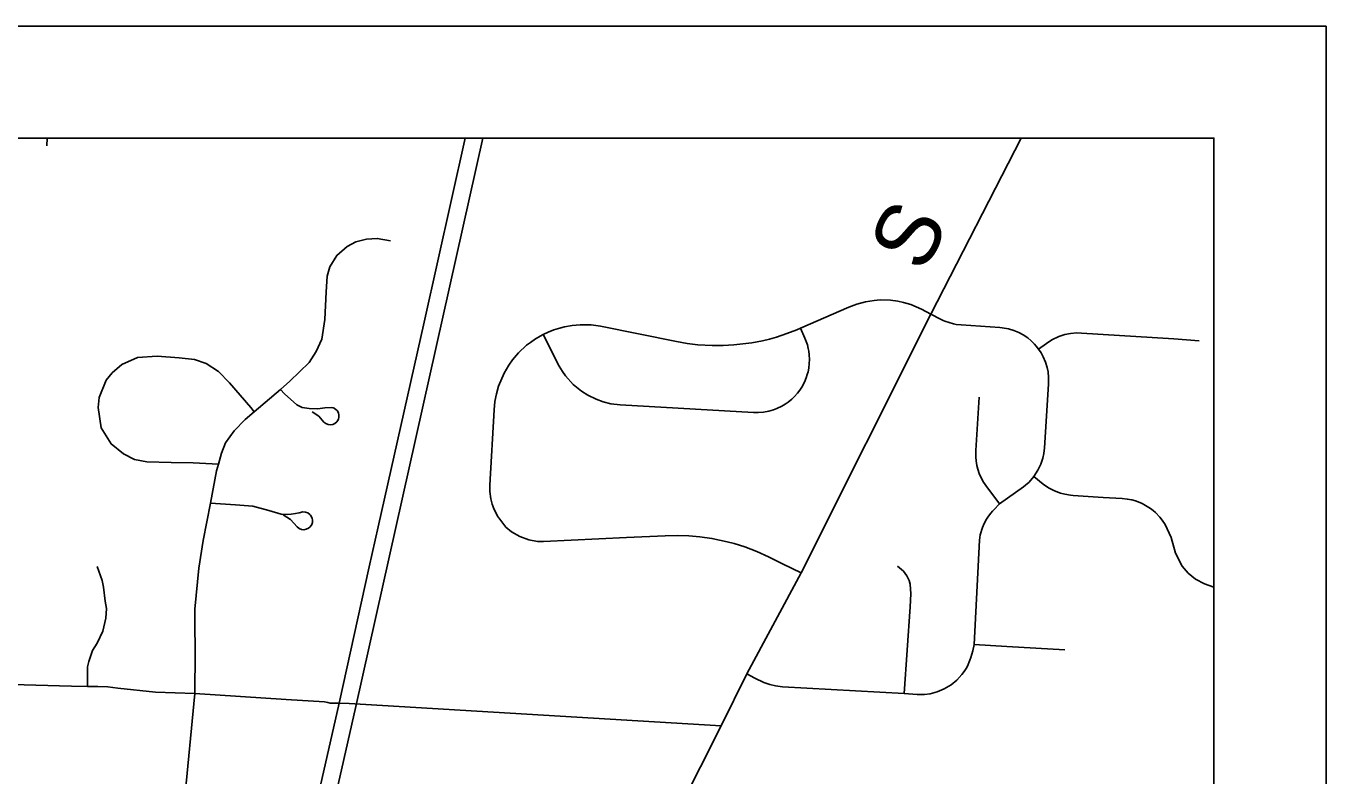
# Model space of a CAD drawing. Extents: x 0 to 34, y 0 to 22.
# Drawn here: x 9.258 to 10.418, y 9.615 to 10.284 of the extents above; entities that cross this region are included whole.
import ezdxf

# ---------------------------------------------------------------- set-up
doc = ezdxf.new("R2010")
doc.units = 0
for name, color, linetype in [('GM_X_Corporation', 7, 'Continuous'), ('GM_X_County_Road', 7, 'Continuous'), ('GM_X_County_Road_Text', 7, 'Continuous'), ('GM_X_Rail_Line', 7, 'Continuous'), ('GM_X_State_Route', 7, 'Continuous'), ('GM_X_Township_Road', 7, 'Continuous'), ('SH_Data', 7, 'Continuous')]:
    doc.layers.add(name, color=color, linetype=linetype)

msp = doc.modelspace()

# ---------------------------------------------------------------- linework, layer by layer
at = {"layer": 'GM_X_Corporation'}
for points in [[(10.3182, 6.9963), (10.3182, 10.1841), (3.5182, 10.1841)], [(10.3182, 6.9963), (10.3182, 10.1841), (8.0168, 10.1841), (8.012, 10.1113), (7.9906, 9.8037), (7.9854, 9.7171), (7.9173, 8.8475), (7.9043, 8.6471), (7.8824, 8.2446), (7.8769, 8.1664), (7.8619, 7.9568), (7.8248, 7.359), (7.8118, 7.1421)]]:
    msp.add_lwpolyline(points, dxfattribs=at)
at = {"layer": 'GM_X_County_Road'}
msp.add_lwpolyline([(9.2983, 8.492), (9.3206, 8.5378), (9.4763, 8.8512), (9.532, 8.9642), (9.6643, 9.2319), (9.7654, 9.4338), (9.7887, 9.4806), (9.823, 9.5499), (9.8784, 9.6595), (9.9012, 9.7059), (9.9498, 9.7963), (10.0655, 10.0271), (10.1462, 10.1841)], dxfattribs=at)
at = {"layer": 'GM_X_Rail_Line'}
msp.add_lwpolyline([(8.9712, 7.0765), (9.0871, 7.5941), (9.3068, 8.5932), (9.5523, 9.677), (9.6655, 10.1841)], dxfattribs=at)
at = {"layer": 'GM_X_State_Route'}
for points in [[(9.5722, 9.8371), (9.5895, 9.9139), (9.6132, 10.0197), (9.6499, 10.1841)], [(9.5019, 9.5239), (9.5372, 9.6798), (9.5642, 9.8016), (9.5722, 9.8371)]]:
    msp.add_lwpolyline(points, dxfattribs=at)
at = {"layer": 'GM_X_Township_Road'}
for p, q in [((9.2764, 10.1771), (9.2768, 10.1841)), ((9.4087, 9.725), (9.4086, 9.7521)), ((9.4084, 9.6884), (9.4087, 9.725))]:
    msp.add_line(p, q, dxfattribs=at)
for points in [[(9.4086, 9.7521), (9.4086, 9.7638), (9.4122, 9.8004), (9.4158, 9.825), (9.4224, 9.8583), (9.4278, 9.8873), (9.4295, 9.8931), (9.4324, 9.903), (9.436, 9.9121), (9.4435, 9.9228), (9.4534, 9.933), (9.4616, 9.9399), (9.4849, 9.9599), (9.4932, 9.9671), (9.5106, 9.9838), (9.5168, 9.9936), (9.5218, 10.0047), (9.5246, 10.0221), (9.5257, 10.0468), (9.5266, 10.0608), (9.529, 10.0691), (9.5353, 10.0794), (9.5445, 10.0875), (9.5522, 10.0915), (9.5616, 10.0938), (9.5714, 10.0946), (9.5831, 10.0924)], [(9.68, 9.8451), (9.6794, 9.8459), (9.6757, 9.8528), (9.6739, 9.8574), (9.6726, 9.8622), (9.6718, 9.8687), (9.6717, 9.8745), (9.6756, 9.9417), (9.6764, 9.9491), (9.6777, 9.956), (9.6797, 9.9627), (9.6846, 9.9743), (9.6889, 9.9816), (9.6921, 9.9862), (9.6975, 9.9924), (9.7047, 9.9992), (9.708, 10.0018), (9.7126, 10.0049), (9.7194, 10.0088), (9.7238, 10.0109), (9.729, 10.013), (9.733, 10.0143), (9.7385, 10.0157), (9.7454, 10.0169), (9.7524, 10.0175), (9.758, 10.0176), (9.7622, 10.0174), (9.7705, 10.0163), (9.8384, 10.0026), (9.848, 10.0009), (9.8576, 9.9997), (9.8704, 9.999), (9.8801, 9.999), (9.8897, 9.9995), (9.9057, 10.0015), (9.9152, 10.0033), (9.9215, 10.0048), (9.9277, 10.0066), (9.9369, 10.0096), (9.9459, 10.013), (9.9492, 10.0145), (9.9922, 10.0333), (9.9994, 10.036), (10.007, 10.0381), (10.0149, 10.0393), (10.0202, 10.0397), (10.0294, 10.0394), (10.0359, 10.0385), (10.0411, 10.0374), (10.0475, 10.0355), (10.0572, 10.0314), (10.0655, 10.0271)], [(9.9012, 9.7059), (9.9084, 9.7023), (9.9165, 9.6984), (9.9217, 9.6965), (9.9269, 9.6952), (9.933, 9.6945), (10.0418, 9.6884), (10.0533, 9.6875), (10.0599, 9.6876), (10.0648, 9.6883), (10.0712, 9.69), (10.0773, 9.6925), (10.0836, 9.6963), (10.0887, 9.7005), (10.0932, 9.7054), (10.0951, 9.708), (10.0969, 9.7108), (10.0981, 9.7129), (10.1004, 9.7182), (10.1012, 9.7205), (10.1029, 9.7266), (10.104, 9.7323), (10.1088, 9.8254), (10.1096, 9.8302), (10.1116, 9.8365), (10.1132, 9.8403), (10.1152, 9.8439), (10.117, 9.8467), (10.1189, 9.8493), (10.1205, 9.8512), (10.1217, 9.8524), (10.1267, 9.8576), (10.1481, 9.8728), (10.15, 9.8744), (10.1531, 9.8772), (10.1575, 9.882), (10.1611, 9.8879), (10.1636, 9.8932), (10.1653, 9.8986), (10.1663, 9.9027), (10.1669, 9.9077), (10.1706, 9.9646), (10.1706, 9.9705), (10.1701, 9.9754), (10.1693, 9.9795), (10.1678, 9.9842), (10.1658, 9.9888), (10.1639, 9.9925), (10.1617, 9.9958), (10.1596, 9.9984), (10.158, 10.0002), (10.155, 10.0031), (10.1519, 10.0058), (10.1478, 10.0085), (10.1441, 10.0105), (10.1396, 10.0124), (10.1348, 10.0138), (10.1291, 10.0148), (10.1269, 10.015), (10.0925, 10.0174), (10.0882, 10.0179), (10.0858, 10.0183), (10.0818, 10.0194), (10.0779, 10.0208), (10.0764, 10.0214), (10.0742, 10.0225), (10.0655, 10.0271)], [(9.7194, 10.0088), (9.7337, 9.9807), (9.7367, 9.9757), (9.7394, 9.972), (9.7463, 9.9642), (9.7535, 9.9583), (9.7593, 9.9546), (9.7666, 9.951), (9.7731, 9.9487), (9.7799, 9.9471), (9.7882, 9.9461), (9.9071, 9.9392), (9.9112, 9.9392), (9.9161, 9.9396), (9.921, 9.9405), (9.925, 9.9416), (9.928, 9.9428), (9.9325, 9.945), (9.9354, 9.9466), (9.9381, 9.9485), (9.9413, 9.9511), (9.9437, 9.9534), (9.9464, 9.9565), (9.9484, 9.9591), (9.9502, 9.9619), (9.9526, 9.9663), (9.9542, 9.9701), (9.9552, 9.9732), (9.9559, 9.9756), (9.9565, 9.9788), (9.957, 9.9829), (9.9571, 9.9865), (9.9569, 9.9906), (9.9565, 9.9939), (9.9561, 9.9963), (9.9553, 9.9995), (9.9543, 10.0027), (9.9531, 10.0055), (9.9492, 10.0145)], [(10.1617, 9.9958), (10.1686, 10.0009), (10.1736, 10.0042), (10.1796, 10.007), (10.1852, 10.0088), (10.19, 10.0097), (10.1958, 10.0102), (10.1999, 10.0101), (10.2823, 10.0049), (10.3049, 10.0033)], [(9.4295, 9.8931), (9.4071, 9.8942), (9.3873, 9.8946), (9.3658, 9.8952), (9.3547, 9.8974), (9.3447, 9.9023), (9.3337, 9.9112), (9.325, 9.9254), (9.3222, 9.9436), (9.3232, 9.9527), (9.3295, 9.9682), (9.3347, 9.9745), (9.3434, 9.982), (9.3572, 9.9884), (9.3748, 9.9895), (9.3945, 9.988), (9.4081, 9.9866), (9.4186, 9.9831), (9.4296, 9.9758), (9.4395, 9.9656), (9.4584, 9.9438), (9.4616, 9.9399)], [(9.4849, 9.9599), (9.4885, 9.956), (9.4996, 9.946), (9.5044, 9.9438), (9.5107, 9.9427), (9.5182, 9.9426), (9.5244, 9.9433), (9.5304, 9.9438), (9.532, 9.9434), (9.533, 9.943), (9.5347, 9.9417), (9.5355, 9.9409), (9.5366, 9.939), (9.5371, 9.9369), (9.5371, 9.9348), (9.5368, 9.9337), (9.5365, 9.9327), (9.5353, 9.9309), (9.5336, 9.9294), (9.5317, 9.9285), (9.5295, 9.9282), (9.5274, 9.9284), (9.5254, 9.9293), (9.5237, 9.9306), (9.5193, 9.9359), (9.5133, 9.9397)], [(10.1267, 9.8576), (10.1146, 9.874), (10.1119, 9.8781), (10.1086, 9.8848), (10.1073, 9.8887), (10.1065, 9.892), (10.1058, 9.896), (10.1055, 9.8994), (10.1055, 9.9052), (10.1086, 9.9528)], [(10.1575, 9.882), (10.1658, 9.8752), (10.1705, 9.872), (10.1757, 9.8693), (10.1811, 9.8673), (10.1851, 9.8663), (10.19, 9.8655), (10.1926, 9.8653), (10.2192, 9.8635), (10.2361, 9.8624), (10.2408, 9.862), (10.2448, 9.8612), (10.248, 9.8603), (10.2519, 9.8589), (10.2542, 9.8579), (10.2572, 9.8563), (10.2614, 9.8537), (10.264, 9.8517), (10.2659, 9.85), (10.2699, 9.8459), (10.2719, 9.8433), (10.2747, 9.8392), (10.2799, 9.8277), (10.2837, 9.8138), (10.2898, 9.8021), (10.2952, 9.7959), (10.3016, 9.7906), (10.3096, 9.7862), (10.3182, 9.7835)], [(9.4224, 9.8583), (9.4447, 9.8568), (9.4603, 9.8555), (9.4747, 9.8518), (9.4856, 9.8484), (9.4908, 9.8483), (9.4944, 9.8485), (9.4983, 9.8491), (9.5016, 9.8498), (9.5049, 9.8506), (9.5074, 9.8504), (9.5094, 9.8496), (9.5112, 9.8483), (9.5119, 9.8475), (9.513, 9.8456), (9.5133, 9.8445), (9.5135, 9.8434), (9.5134, 9.8412), (9.5128, 9.8392), (9.5116, 9.8373), (9.5099, 9.8359), (9.5079, 9.835), (9.5057, 9.8346), (9.5036, 9.8349), (9.5015, 9.8357), (9.4998, 9.8371), (9.494, 9.8438), (9.4874, 9.8478)], [(9.9498, 9.7963), (9.9332, 9.8042), (9.9207, 9.8105), (9.9102, 9.8152), (9.8994, 9.8193), (9.89, 9.8222), (9.8836, 9.8239), (9.87, 9.8268), (9.8592, 9.8283), (9.8494, 9.8292), (9.8395, 9.8295), (9.8283, 9.8293), (9.7938, 9.8276), (9.7196, 9.824), (9.7143, 9.8242), (9.7066, 9.8256), (9.6985, 9.8285), (9.6911, 9.8328), (9.686, 9.837), (9.68, 9.8451)], [(9.3126, 9.6948), (9.3127, 9.7124), (9.314, 9.717), (9.3173, 9.7269), (9.3212, 9.7335), (9.3265, 9.744), (9.3291, 9.7558), (9.3297, 9.7644), (9.3284, 9.771), (9.3271, 9.7834), (9.3258, 9.7894), (9.3212, 9.8019)], [(10.0418, 9.6884), (10.047, 9.7658), (10.0475, 9.7775), (10.047, 9.7859), (10.0461, 9.7893), (10.044, 9.7934), (10.0411, 9.7976), (10.0358, 9.8022)], [(8.5147, 9.7403), (8.5272, 9.7387), (8.5485, 9.7378), (8.8372, 9.7213), (9.0127, 9.7109), (9.086, 9.7066), (9.2241, 9.6971), (9.2983, 9.695), (9.3126, 9.6948), (9.322, 9.6946), (9.3308, 9.6943), (9.3399, 9.6932), (9.3734, 9.6897), (9.4084, 9.6884), (9.49, 9.6832), (9.5242, 9.6809), (9.5272, 9.6804)], [(10.104, 9.7323), (10.1333, 9.7303), (10.1851, 9.7275)], [(9.3829, 9.3994), (9.3934, 9.5017), (9.3993, 9.5927), (9.4084, 9.6884)], [(9.5272, 9.6804), (9.5293, 9.68), (9.5372, 9.6798), (9.5464, 9.6796), (9.8784, 9.6595)]]:
    msp.add_lwpolyline(points, dxfattribs=at)
at = {"layer": 'SH_Data'}
for p, q in [((3.4182, 10.2841), (10.4182, 10.2841)), ((10.4182, 10.2841), (10.4182, 3.2841)), ((3.5182, 10.1841), (10.3182, 10.1841)), ((10.3182, 10.1841), (10.3182, 3.3841))]:
    msp.add_line(p, q, dxfattribs=at)

# ---------------------------------------------------------------- texts
at = {"layer": 'GM_X_County_Road_Text'}
msp.add_text('S', height=0.0568, rotation=62.8768, dxfattribs=at).set_placement((10.0589, 10.0624))

doc.saveas('drawing.dxf')
